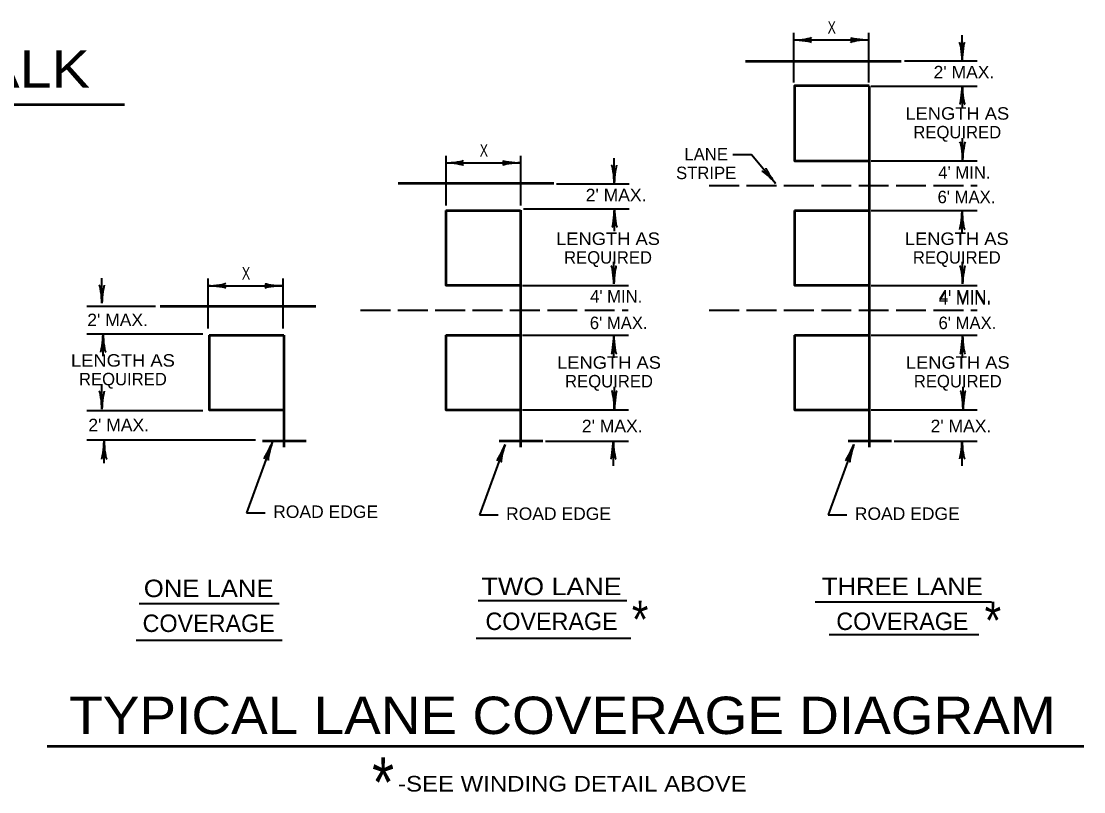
# Model space of a CAD drawing. Extents: x -58 to 622, y -372 to 68.
# Drawn here: x 200.3 to 370.9, y -225.9 to -102.2 of the extents above; entities that cross this region are included whole.
import ezdxf
from ezdxf.enums import TextEntityAlignment as Align

# ---------------------------------------------------------------- set-up
doc = ezdxf.new("R2010")
doc.units = 0
doc.header["$LTSCALE"] = 0.8
doc.linetypes.add('LONG_DASHED', pattern=[7.5, 6, -1.5])
doc.layers.add('1', color=7, linetype='Continuous', lineweight=35)

msp = doc.modelspace()

# ---------------------------------------------------------------- linework, layer by layer
at = {"layer": '1'}
for p, q in [((324.2692, -105.2347), (336.2847, -105.2347)), ((324.3488, -112.0774), (324.3488, -104.0774)), ((336.3488, -112.0774), (336.3488, -104.0774)), ((351.3414, -108.4852), (351.3414, -104.4852)), ((342.092, -108.5765), (353.7611, -108.5765)), ((336.7611, -112.6343), (353.7611, -112.6343)), ((351.3812, -116.186), (351.3812, -112.686)), ((351.4209, -124.4781), (351.4209, -120.9781)), ((268.4928, -131.8101), (268.4928, -123.8101)), ((280.4928, -131.8101), (280.4928, -123.8101)), ((295.4853, -128.2178), (295.4853, -124.2178)), ((268.4132, -124.9674), (280.4287, -124.9674)), ((336.7611, -124.6343), (353.7611, -124.6343)), ((286.2359, -128.3092), (297.905, -128.3092)), ((280.905, -132.367), (297.905, -132.367)), ((295.5251, -135.9187), (295.5251, -132.4187)), ((336.7611, -132.6343), (353.7611, -132.6343)), ((351.3414, -136.2764), (351.3414, -132.7764)), ((295.4209, -144.3696), (295.4209, -140.8696)), ((351.4209, -144.3696), (351.4209, -140.8696)), ((213.2128, -147.4731), (213.2128, -143.4731)), ((230.221, -144.7001), (242.2365, -144.7001)), ((230.3006, -151.5427), (230.3006, -143.5427)), ((242.3006, -151.5427), (242.3006, -143.5427)), ((280.7611, -144.6343), (297.7611, -144.6343)), ((336.7611, -144.6343), (353.7611, -144.6343)), ((221.8063, -147.9942), (210.8156, -147.9942)), ((229.4447, -152.45), (210.8156, -152.45)), ((213.4117, -155.9697), (213.4117, -152.4697)), ((280.7611, -152.6343), (297.7611, -152.6343)), ((295.4209, -156.2476), (295.4209, -152.7476)), ((336.7611, -152.6343), (353.7611, -152.6343)), ((351.4209, -156.2476), (351.4209, -152.7476)), ((213.2128, -164.5004), (213.2128, -160.5004)), ((295.5005, -164.4203), (295.5005, -160.9203)), ((351.5005, -164.4203), (351.5005, -160.9203)), ((229.4447, -164.7682), (210.8156, -164.7682)), ((280.7611, -164.6343), (297.7611, -164.6343)), ((336.7611, -164.6343), (353.7611, -164.6343)), ((237.8789, -169.4774), (210.8156, -169.4774)), ((213.5708, -173.1562), (213.5708, -169.6562)), ((240.5595, -169.8673), (236.4582, -181.1357)), ((277.9561, -170.1856), (273.8548, -181.4539)), ((284.421, -169.6232), (297.7611, -169.6232)), ((295.3413, -173.6157), (295.3413, -169.6157)), ((333.9561, -170.1856), (329.8548, -181.4539)), ((340.421, -169.6232), (353.7611, -169.6232)), ((351.3413, -173.6157), (351.3413, -169.6157)), ((236.4582, -181.1357), (239.4582, -181.1357)), ((273.8548, -181.4539), (276.8548, -181.4539)), ((329.8548, -181.4539), (332.8548, -181.4539)), ((219.2203, -195.6742), (241.6589, -195.6742)), ((273.6443, -195.1968), (297.5145, -195.1968)), ((327.7501, -195.4353), (356.0764, -195.4353)), ((273.3261, -201.2439), (298.1557, -201.2439)), ((329.9779, -200.6867), (354.0093, -200.6867)), ((218.7429, -201.5622), (242.1358, -201.5622))]:
    msp.add_line(p, q, dxfattribs=at)
at = {"layer": '1', "lineweight": 53}
for p, q in [((316.5513, -108.6561), (341.5513, -108.6561)), ((336.4429, -112.6152), (336.4429, -170.6152)), ((0.8544, -115.6087), (216.8702, -115.6087)), ((260.7747, -128.2296), (285.7747, -128.2296)), ((268.4429, -132.6152), (280.4429, -132.6152)), ((280.4429, -132.5694), (280.4429, -170.6152)), ((280.4429, -132.649), (280.4429, -170.6152)), ((324.4429, -132.6152), (336.4429, -132.6152)), ((222.5826, -147.9622), (247.5826, -147.9622)), ((230.4429, -152.6152), (242.4429, -152.6152)), ((242.4429, -152.6152), (242.4429, -170.6152)), ((242.4429, -152.6292), (242.4429, -170.6152)), ((268.4429, -152.6152), (280.4429, -152.6152)), ((324.4429, -152.6152), (336.4429, -152.6152)), ((239.0214, -169.5842), (246.0214, -169.5842)), ((277.0214, -169.5842), (284.0214, -169.5842)), ((333.0214, -169.5842), (340.0214, -169.5842)), ((204.4208, -218.5891), (370.8755, -218.5891))]:
    msp.add_line(p, q, dxfattribs=at)
at = {"layer": '1', "linetype": 'LONG_DASHED'}
for p, q in [((310.7429, -128.6062), (353.7429, -128.6062)), ((254.7429, -148.6062), (297.7429, -148.6062)), ((310.7429, -148.6062), (353.7429, -148.6062))]:
    msp.add_line(p, q, dxfattribs=at)
at = {"layer": '1', "lineweight": 53}
for points in [[(336.4429, -112.6152), (324.4429, -112.6152), (324.4429, -124.6152), (336.4429, -124.6152)], [(268.4429, -132.6152), (268.4429, -144.6152), (280.4429, -144.6152)], [(324.4429, -132.6152), (324.4429, -144.6152), (336.4429, -144.6152)], [(230.4429, -152.6152), (230.4429, -164.6152), (242.4429, -164.6152)], [(268.4429, -152.6152), (268.4429, -164.6152), (280.4429, -164.6152)], [(324.4429, -152.6152), (324.4429, -164.6152), (336.4429, -164.6152)]]:
    msp.add_lwpolyline(points, dxfattribs=at)
at = {"layer": '1'}
msp.add_lwpolyline([(321.3846, -128.2541), (317.5278, -123.6578), (314.5278, -123.6578)], dxfattribs=at)
at = {"layer": '1', "lineweight": 40}
for centre, major_axis, ratio, start_param, end_param in [((325.3898, -105.4464), (1.7565, -0.1757), 0.07063, 6.28230741, 8.55970261), ((325.3604, -104.9585), (-1.7857, -0.1562), 0.122415, 0.89635335, 3.14159265), ((335.1936, -105.511), (1.7857, 0.1562), 0.122415, 0.89635335, 3.14159265), ((335.1936, -105.511), (1.7857, 0.1562), 0.122415, 0.89635335, 3.14159265), ((335.1642, -105.0231), (1.7565, -0.1757), 0.07063, 3.14071475, 5.41810995), ((335.1642, -105.0231), (1.7565, -0.1757), 0.07063, 3.14071475, 5.41810995), ((351.0651, -107.394), (0.1562, -1.7857), 0.122415, 0.89635335, 3.14159265), ((351.553, -107.3647), (0.1757, 1.7565), 0.07063, 6.28230741, 8.55970261), ((351.1696, -113.8065), (-0.1757, -1.7565), 0.07063, 6.28230741, 8.55970261), ((351.6575, -113.7772), (-0.1562, 1.7857), 0.122415, 0.89635335, 3.14159265), ((351.1446, -123.3869), (0.1562, -1.7857), 0.122415, 0.89635335, 3.14159265), ((351.6325, -123.3576), (0.1757, 1.7565), 0.07063, 6.28230741, 8.55970261), ((269.5044, -124.6911), (-1.7857, -0.1562), 0.122415, 0.89635335, 3.14159265), ((269.5337, -125.179), (1.7565, -0.1757), 0.07063, 6.28230741, 8.55970261), ((279.3375, -125.2437), (1.7857, 0.1562), 0.122415, 0.89635335, 3.14159265), ((279.3375, -125.2437), (1.7857, 0.1562), 0.122415, 0.89635335, 3.14159265), ((279.3082, -124.7558), (1.7565, -0.1757), 0.07063, 3.14071475, 5.41810995), ((279.3082, -124.7558), (1.7565, -0.1757), 0.07063, 3.14071475, 5.41810995), ((295.209, -127.1266), (0.1562, -1.7857), 0.122415, 0.89635335, 3.14159265), ((295.6969, -127.0973), (0.1757, 1.7565), 0.07063, 6.28230741, 8.55970261), ((320.8264, -127.2597), (0.9945, -1.4584), 0.07063, 3.14071475, 5.41810995), ((320.4715, -127.5958), (1.2674, -1.2675), 0.122415, 0.89635335, 3.14159265), ((295.3135, -133.5392), (-0.1757, -1.7565), 0.07063, 6.28230741, 8.55970261), ((295.8014, -133.5099), (-0.1562, 1.7857), 0.122415, 0.89635335, 3.14159265), ((351.1298, -133.8969), (-0.1757, -1.7565), 0.07063, 6.28230741, 8.55970261), ((351.6177, -133.8676), (-0.1562, 1.7857), 0.122415, 0.89635335, 3.14159265), ((295.1446, -143.2784), (0.1562, -1.7857), 0.122415, 0.89635335, 3.14159265), ((295.6325, -143.2491), (0.1757, 1.7565), 0.07063, 6.28230741, 8.55970261), ((351.1446, -143.2784), (0.1562, -1.7857), 0.122415, 0.89635335, 3.14159265), ((351.6325, -143.2491), (0.1757, 1.7565), 0.07063, 6.28230741, 8.55970261), ((212.9365, -146.3819), (0.1562, -1.7857), 0.122415, 0.89635335, 3.14159265), ((213.4244, -146.3526), (0.1757, 1.7565), 0.07063, 6.28230741, 8.55970261), ((231.3415, -144.9117), (1.7565, -0.1757), 0.07063, 6.28230741, 8.55970261), ((231.3122, -144.4238), (-1.7857, -0.1562), 0.122415, 0.89635335, 3.14159265), ((241.1453, -144.9764), (1.7857, 0.1562), 0.122415, 0.89635335, 3.14159265), ((241.116, -144.4885), (1.7565, -0.1757), 0.07063, 3.14071475, 5.41810995), ((213.2001, -153.5902), (-0.1757, -1.7565), 0.07063, 6.28230741, 8.55970261), ((213.688, -153.5609), (-0.1562, 1.7857), 0.122415, 0.89635335, 3.14159265), ((295.2093, -153.8681), (-0.1757, -1.7565), 0.07063, 6.28230741, 8.55970261), ((295.6972, -153.8388), (-0.1562, 1.7857), 0.122415, 0.89635335, 3.14159265), ((351.2093, -153.8681), (-0.1757, -1.7565), 0.07063, 6.28230741, 8.55970261), ((351.6972, -153.8388), (-0.1562, 1.7857), 0.122415, 0.89635335, 3.14159265), ((212.9365, -163.4092), (0.1562, -1.7857), 0.122415, 0.89635335, 3.14159265), ((213.4244, -163.3799), (0.1757, 1.7565), 0.07063, 6.28230741, 8.55970261), ((295.2242, -163.3291), (0.1562, -1.7857), 0.122415, 0.89635335, 3.14159265), ((295.7121, -163.2998), (0.1757, 1.7565), 0.07063, 6.28230741, 8.55970261), ((351.2242, -163.3291), (0.1562, -1.7857), 0.122415, 0.89635335, 3.14159265), ((351.7121, -163.2998), (0.1757, 1.7565), 0.07063, 6.28230741, 8.55970261), ((213.3592, -170.7767), (-0.1757, -1.7565), 0.07063, 6.28230741, 8.55970261), ((213.8471, -170.7474), (-0.1562, 1.7857), 0.122415, 0.89635335, 3.14159265), ((239.9774, -170.8479), (0.7658, 1.5905), 0.07063, 3.14071475, 5.41810995), ((240.4459, -170.9872), (0.464, 1.7314), 0.122415, 0.89635335, 3.14159265), ((277.374, -171.1661), (0.7658, 1.5905), 0.07063, 3.14071475, 5.41810995), ((277.8425, -171.3055), (0.464, 1.7314), 0.122415, 0.89635335, 3.14159265), ((295.1297, -170.7362), (-0.1757, -1.7565), 0.07063, 6.28230741, 8.55970261), ((295.6176, -170.7069), (-0.1562, 1.7857), 0.122415, 0.89635335, 3.14159265), ((333.374, -171.1661), (0.7658, 1.5905), 0.07063, 3.14071475, 5.41810995), ((333.8425, -171.3055), (0.464, 1.7314), 0.122415, 0.89635335, 3.14159265), ((351.1297, -170.7362), (-0.1757, -1.7565), 0.07063, 6.28230741, 8.55970261), ((351.6176, -170.7069), (-0.1562, 1.7857), 0.122415, 0.89635335, 3.14159265)]:
    msp.add_ellipse(centre, major_axis=major_axis, ratio=ratio, start_param=start_param, end_param=end_param, dxfattribs=at)

# ---------------------------------------------------------------- texts
at = {"layer": '1'}
for s, height, width, p in [('X', 2, 0.75, (329.7391, -104.2271)), ('TYPICAL SECTION IN GUTTER AND SIDEWALK', 6, 1.15, (4.6777, -112.8777)), ("2' MAX.", 2, 1.05, (346.7663, -111.388)), ('X', 2, 0.75, (273.883, -123.9597)), ("2' MAX.", 2, 1.05, (290.9102, -131.1207)), ('X', 2, 0.75, (235.6908, -143.6924)), ("2' MAX.", 2, 1.05, (210.8655, -151.1716)), ("2' MAX.", 2, 1.05, (211.04, -168.0395)), ("2' MAX.", 2, 1.05, (290.2889, -168.1987)), ("2' MAX.", 2, 1.05, (346.2889, -168.1987)), ('ROAD EDGE', 2, 1.05, (240.7186, -181.9615)), ('ROAD EDGE', 2, 1.05, (278.1152, -182.2798)), ('ROAD EDGE', 2, 1.05, (334.1152, -182.2798)), ('*', 6, 0.85, (298.31, -201.2437)), ('*', 6, 0.85, (354.962, -201.4027))]:
    msp.add_text(s, height=height, dxfattribs=dict(at, width=width)).set_placement(p)
for s, height, width, p in [('LENGTH AS', 2, 1.1, (350.5656, -118.0289)), ('LENGTH AS', 2, 1.1, (294.486, -138.1393)), ('LENGTH AS', 2, 1.1, (350.486, -138.1393)), ('LENGTH AS', 2, 1.1, (216.5897, -157.673)), ('LENGTH AS', 2, 1.1, (294.6451, -158.0111)), ('LENGTH AS', 2, 1.1, (350.6451, -158.0111)), ('ONE LANE', 2.8, 1.1, (230.3598, -194.6721)), ('TWO LANE', 2.8, 1.15, (285.4203, -194.3538)), ('THREE LANE', 2.8, 1.1, (341.754, -194.3537)), ('TYPICAL LANE COVERAGE DIAGRAM', 6, 1.1, (287.1707, -216.6561)), ('*', 8, 0.85, (258.3675, -228.3973)), ('-SEE WINDING DETAIL ABOVE', 2.5, 1.15, (288.7621, -225.8862))]:
    msp.add_text(s, height=height, dxfattribs=dict(at, width=width)).set_placement(p, align=Align.CENTER)
for s, height, p in [('REQUIRED', 2, (350.5656, -121.0289)), ('LANE', 2, (310.2452, -124.5714)), ('STRIPE', 2, (310.2452, -127.5714)), ('REQUIRED', 2, (294.486, -141.1393)), ('REQUIRED', 2, (350.486, -141.1393)), ('REQUIRED', 2, (216.5897, -160.673)), ('REQUIRED', 2, (294.6451, -161.0111)), ('REQUIRED', 2, (350.6451, -161.0111)), ('COVERAGE', 2.8, (230.3598, -200.2721)), ('COVERAGE', 2.8, (285.4203, -199.9538)), ('COVERAGE', 2.8, (341.754, -199.9537))]:
    msp.add_text(s, height=height, dxfattribs=at).set_placement(p, align=Align.CENTER)
for s, p in [("4' MIN.", (347.5222, -127.4984)), ("6' MAX.", (347.4028, -131.437)), ("4' MIN.", (291.6018, -147.3902)), ("4' MIN.", (347.6018, -147.3902)), ("4' MIN.", (347.6018, -147.7084)), ("6' MAX.", (291.5619, -151.647)), ("6' MAX.", (347.5619, -151.647))]:
    msp.add_text(s, height=2, dxfattribs=at).set_placement(p)

doc.saveas('drawing.dxf')
